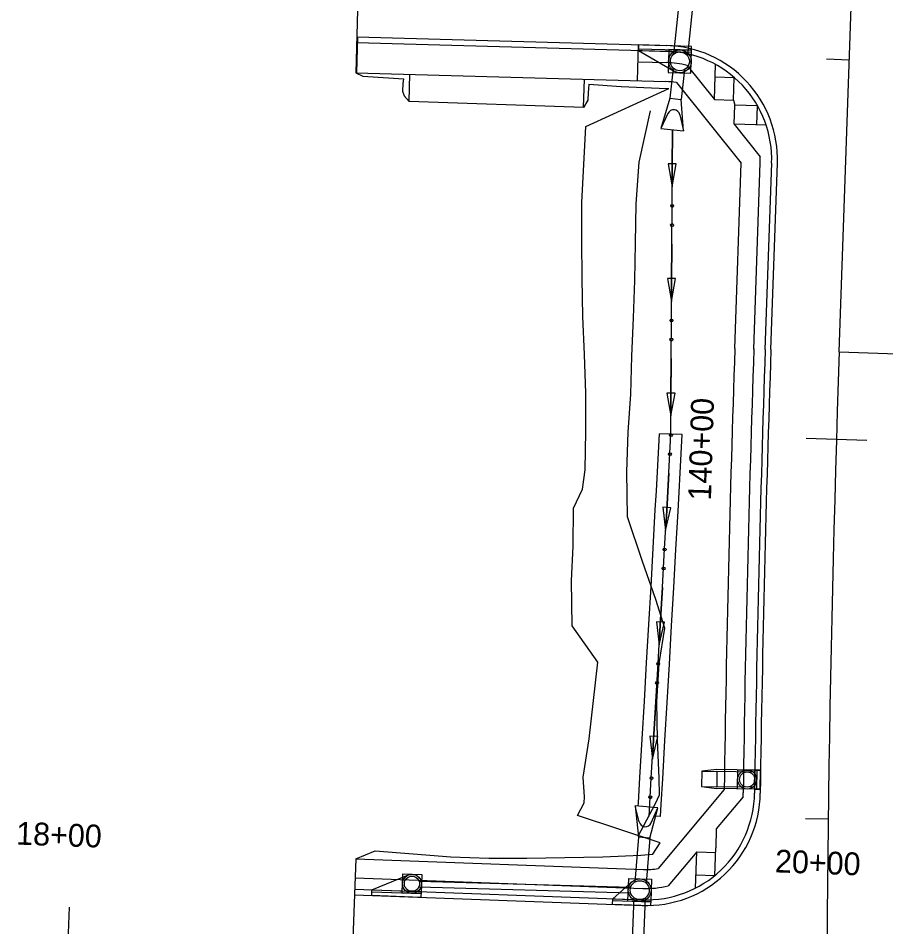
# Model space of a CAD drawing. Extents: x 979959 to 994833, y 1835619 to 1845316.
# Drawn here: x 992259.7 to 992488.3, y 1842625.6 to 1842864.9 of the extents above; entities that cross this region are included whole.
import ezdxf

# ---------------------------------------------------------------- set-up
doc = ezdxf.new("R2010")
doc.units = 0
for name, color, linetype in [('Future 5 Lane Construction Limits', 7, 'Continuous'), ('R_Drainage', 7, 'Continuous'), ('R_Horz Alg', 7, 'Continuous'), ('R_Horz Alg Annot', 7, 'Continuous'), ('R_Horz Alg Stationing', 7, 'Continuous'), ('R_Proposed Const Limits', 7, 'Continuous'), ('R_Proposed Road', 7, 'Continuous'), ('R_Special Ditch', 7, 'Continuous')]:
    doc.layers.add(name, color=color, linetype=linetype)

msp = doc.modelspace()

# ---------------------------------------------------------------- linework, layer by layer
at = {"layer": 'Future 5 Lane Construction Limits'}
for points in [[(992430.04, 1842704.32), (992427.7, 1842711.79), (992424.16, 1842721.86), (992420.25, 1842733.57), (992420.08, 1842745.46), (992420.46, 1842755.94), (992421.13, 1842765.94), (992421.36, 1842775.9), (992421.82, 1842785.98), (992422.18, 1842795.84), (992422.35, 1842805.73), (992422.51, 1842816.01), (992423.32, 1842826.99), (992426.26, 1842840.54)], [(992423.06, 1842649.49), (992427.64, 1842658.13), (992428.68, 1842660.39), (992428.57, 1842664.74), (992428.12, 1842674.83), (992428.01, 1842684.91), (992428.54, 1842694.98), (992430.04, 1842704.32)]]:
    msp.add_lwpolyline(points, dxfattribs=at)
at = {"layer": 'R_Drainage'}
for p, q in [((992436.04, 1842890.55), (992432.38, 1842855.46)), ((992439.73, 1842890.55), (992436.03, 1842855.08)), ((992423.11, 1842856.41), (992432.53, 1842850.98)), ((992423.12, 1842856.91), (992437.12, 1842856.49)), ((992432.31, 1842851.76), (992431.42, 1842843.86)), ((992435.29, 1842851.43), (992434.4, 1842843.53)), ((992431.42, 1842843.86), (992429.02, 1842835.93)), ((992431.42, 1842843.86), (992434.4, 1842843.53)), ((992434.98, 1842835.26), (992434.4, 1842843.53)), ((992430.9, 1842839.88), (992429.02, 1842835.93)), ((992434.03, 1842839.52), (992434.98, 1842835.26)), ((992429.02, 1842835.93), (992434.98, 1842835.26)), ((992434.67, 1842755.3), (992428.67, 1842755.48)), ((992439.79, 1842666.58), (992439.73, 1842662.58)), ((992443.8, 1842667.03), (992439.79, 1842666.58)), ((992439.79, 1842666.58), (992443.79, 1842666.53)), ((992443.79, 1842666.53), (992443.73, 1842662.53)), ((992453.79, 1842666.38), (992443.79, 1842666.53)), ((992454.3, 1842666.87), (992443.8, 1842667.03)), ((992449.22, 1842661.95), (992449.3, 1842666.95)), ((992453.79, 1842666.38), (992453.73, 1842662.38)), ((992454.3, 1842666.87), (992454.22, 1842661.87)), ((992439.73, 1842662.58), (992443.72, 1842662.03)), ((992439.73, 1842662.58), (992443.73, 1842662.53)), ((992454.22, 1842661.87), (992443.72, 1842662.03)), ((992453.73, 1842662.38), (992443.73, 1842662.53)), ((992453.72, 1842661.88), (992455.22, 1842661.86)), ((992428.25, 1842656.97), (992422.27, 1842657.46)), ((992422.27, 1842657.46), (992423.1, 1842649.22)), ((992423.35, 1842653.23), (992422.27, 1842657.46)), ((992426.09, 1842648.97), (992428.25, 1842656.97)), ((992426.49, 1842652.97), (992428.25, 1842656.97)), ((992428.91, 1842654.66), (992427.65, 1842654.73)), ((992423.1, 1842649.22), (992422.19, 1842637.42)), ((992426.09, 1842648.97), (992423.1, 1842649.22)), ((992426.09, 1842648.97), (992425.17, 1842637.09)), ((992361.08, 1842639.56), (992366.07, 1842639.38)), ((992352.92, 1842635.35), (992362.54, 1842639.28)), ((992365.36, 1842637.67), (992421.1, 1842636.09)), ((992416.37, 1842633.03), (992421.48, 1842637.52)), ((992352.9, 1842634.85), (992365.89, 1842634.38)), ((992365.32, 1842636.17), (992421.06, 1842634.59)), ((992416.36, 1842632.53), (992426.35, 1842632.16)), ((992421.89, 1842633.32), (992420.71, 1842601.17)), ((992424.89, 1842633.21), (992423.7, 1842601.06))]:
    msp.add_line(p, q, dxfattribs=at)
for points in [[(992423.11, 1842856.41), (992437.1, 1842855.99), (992437.14, 1842857.49), (992423.15, 1842857.91)], [(992430.94, 1842850.67), (992436.94, 1842850.5), (992437.12, 1842856.49), (992431.12, 1842856.67)], [(992449.22, 1842661.95), (992449.3, 1842666.95), (992454.3, 1842666.87), (992454.22, 1842661.87)], [(992453.72, 1842661.88), (992453.8, 1842666.88), (992455.3, 1842666.86), (992455.22, 1842661.86)], [(992361.08, 1842639.56), (992366.07, 1842639.38), (992365.89, 1842634.38), (992360.89, 1842634.56)], [(992420.57, 1842638.38), (992426.57, 1842638.16), (992426.35, 1842632.16), (992420.35, 1842632.38)], [(992352.92, 1842635.35), (992365.91, 1842634.88), (992365.85, 1842633.38), (992352.86, 1842633.86)], [(992416.37, 1842633.03), (992426.37, 1842632.66), (992426.31, 1842631.16), (992416.32, 1842631.53)]]:
    msp.add_lwpolyline(points, close=True, dxfattribs=at)
for points in [[(992423.07, 1842657.4), (992423.12, 1842658.24), (992423.52, 1842664.95), (992424.12, 1842675.02), (992424.71, 1842685.09), (992425.29, 1842695.16), (992425.87, 1842705.23), (992426.44, 1842715.29), (992427.01, 1842725.36), (992427.57, 1842735.42), (992427.85, 1842740.46), (992428.12, 1842745.49), (992428.67, 1842755.47), (992428.67, 1842755.48)], [(992428.91, 1842654.66), (992429.11, 1842657.88), (992429.51, 1842664.59), (992430.11, 1842674.67), (992430.7, 1842684.74), (992431.28, 1842694.81), (992431.86, 1842704.88), (992432.43, 1842714.95), (992433, 1842725.02), (992433.56, 1842735.09), (992433.84, 1842740.13), (992434.11, 1842745.16), (992434.67, 1842755.3)], [(992455.22, 1842661.86), (992455.3, 1842666.86), (992453.8, 1842666.88), (992453.72, 1842661.88)]]:
    msp.add_lwpolyline(points, dxfattribs=at)
for centre, radius in [((992434.03, 1842853.58), 3), ((992434.03, 1842853.58), 3), ((992434.03, 1842853.58), 2.5), ((992434.03, 1842853.58), 2.5), ((992451.76, 1842664.41), 2.5), ((992451.76, 1842664.41), 2.5), ((992451.76, 1842664.41), 2), ((992451.76, 1842664.41), 2), ((992363.48, 1842636.97), 2.5), ((992363.48, 1842636.97), 2.5), ((992363.48, 1842636.97), 2), ((992363.48, 1842636.97), 2), ((992423.46, 1842635.27), 3), ((992423.46, 1842635.27), 3), ((992423.46, 1842635.27), 2.5), ((992423.46, 1842635.27), 2.5)]:
    msp.add_circle(centre, radius, dxfattribs=at)
for centre, start, end in [((992432.4, 1842839.16), 12.6066, 154.5213), ((992424.96, 1842653.64), 194.3558, 336.2706)]:
    msp.add_arc(centre, 1.67, start, end, dxfattribs=at)
at = {"layer": 'R_Horz Alg'}
msp.add_line((992476.02, 1842777.04), (992513.51, 1843870.41), dxfattribs=at)
msp.add_arc((998202.23, 1842580.69), 5729.58, 178.036106, 183.022805, dxfattribs=at)
at = {"layer": 'R_Horz Alg Annot'}
msp.add_lwpolyline([(992476.02, 1842777.04), (992605.94, 1842772.59)], dxfattribs=at)
at = {"layer": 'R_Horz Alg Stationing'}
for points in [[(992472.66, 1842854.21), (992478.66, 1842854.01)], [(992467.28, 1842754.31), (992483.28, 1842753.82)], [(992467.13, 1842654.17), (992473.13, 1842654.09)], [(992273.19, 1842630.77), (992272.6, 1842614.78)]]:
    msp.add_lwpolyline(points, dxfattribs=at)
at = {"layer": 'R_Proposed Const Limits'}
for points in [[(992348.65, 1842850.57), (992350.54, 1842849.69), (992358.62, 1842849.15), (992361.23, 1842848.96)], [(992361.23, 1842848.96), (992361.06, 1842847.72), (992360.99, 1842845.72), (992361.39, 1842844.45), (992362.7, 1842842.98)], [(992428.81, 1842647.75), (992407.06, 1842654.94), (992408.85, 1842658.31), (992408.88, 1842659.87), (992408.58, 1842665.03), (992410.11, 1842675.12), (992411.32, 1842685.21), (992412.45, 1842695.3), (992405.64, 1842704.9), (992405.52, 1842716.74), (992405.9, 1842725.91), (992406.03, 1842735.91), (992408.42, 1842740.91), (992409.1, 1842745.95), (992409.3, 1842756.06), (992409.31, 1842766.18), (992408.92, 1842776.32), (992408.52, 1842786.37), (992408.33, 1842796.39), (992408.18, 1842806.4), (992408.21, 1842816.4), (992408.74, 1842826.39), (992409.27, 1842836.38), (992431.09, 1842846.43)], [(992410.07, 1842847.57), (992409.98, 1842846.33), (992409.91, 1842845.33), (992409.77, 1842843.33), (992408.67, 1842841.4)], [(992410.07, 1842847.57), (992418.58, 1842846.92), (992428.57, 1842846.54), (992431.09, 1842846.43)], [(992348.71, 1842643.51), (992353.79, 1842645.65), (992363.76, 1842644.86), (992373.74, 1842644.06), (992383.73, 1842643.68), (992393.74, 1842643.73), (992403.75, 1842643.85), (992413.77, 1842644.05), (992423.79, 1842644.51), (992426.92, 1842644.78), (992428.81, 1842647.75)]]:
    msp.add_lwpolyline(points, dxfattribs=at)
at = {"layer": 'R_Proposed Road'}
for p, q in [((992349.99, 1842897.56), (992348.65, 1842850.57)), ((992348.91, 1842850.57), (992349.18, 1842860.06)), ((992348.92, 1842860.07), (992430.59, 1842857.75)), ((992348.88, 1842858.57), (992430.54, 1842856.25)), ((992422.88, 1842848.46), (992423.15, 1842857.96)), ((992423.02, 1842853.46), (992430.46, 1842853.25)), ((992443.17, 1842843.49), (992443.44, 1842852.75)), ((992348.65, 1842850.57), (992430.32, 1842848.25)), ((992362.7, 1842842.98), (992362.9, 1842850.17)), ((992435.95, 1842852.49), (992443.17, 1842843.49)), ((992408.67, 1842841.4), (992408.89, 1842848.86)), ((992433.17, 1842847.97), (992450.21, 1842826.73)), ((992443.34, 1842849.49), (992448.34, 1842849.34)), ((992448.17, 1842843.35), (992448.34, 1842849.34)), ((992408.67, 1842841.4), (992362.7, 1842842.98)), ((992443.17, 1842843.49), (992448.17, 1842843.35)), ((992448.17, 1842843.35), (992448.52, 1842842.04)), ((992448.35, 1842837.04), (992448.52, 1842842.04)), ((992454.52, 1842841.83), (992448.52, 1842842.04)), ((992454.34, 1842836.83), (992454.52, 1842841.83)), ((992456.78, 1842836.75), (992448.35, 1842837.04)), ((992448.35, 1842837.04), (992455.22, 1842828.47)), ((992448.54, 1842777.98), (992450.21, 1842826.73)), ((992453.53, 1842777.81), (992455.22, 1842826.88)), ((992456.53, 1842777.71), (992458.22, 1842826.78)), ((992458.03, 1842777.66), (992459.71, 1842826.73)), ((992445.73, 1842661.75), (992428.28, 1842640.95)), ((992450.68, 1842659.88), (992443.59, 1842651.43)), ((992443.59, 1842651.43), (992443.53, 1842646.43)), ((992438.49, 1842645.35), (992430.97, 1842636.38)), ((992438.14, 1842635.82), (992438.49, 1842645.35)), ((992438.49, 1842645.35), (992443.49, 1842645.17)), ((992443.27, 1842639.17), (992443.53, 1842646.43)), ((992348.71, 1842643.51), (992346.98, 1842596.54)), ((992348.71, 1842643.51), (992424.47, 1842640.74)), ((992348.52, 1842638.52), (992424.28, 1842635.74)), ((992438.27, 1842639.35), (992443.27, 1842639.17)), ((992348.41, 1842635.52), (992424.17, 1842632.74)), ((992348.36, 1842634.02), (992424.12, 1842631.24))]:
    msp.add_line(p, q, dxfattribs=at)
for centre, radius, start, end in [((992429.73, 1842827.76), 30, 358.0361, 88.3694), ((992429.73, 1842827.76), 28.5, 358.0361, 88.3694), ((992429.73, 1842827.76), 25.5, 75.8794, 88.3694), ((992429.73, 1842827.76), 20.5, 80.3487, 88.3694), ((992429.73, 1842827.76), 25.5, 358.0361, 1.6001), ((998202.23, 1842580.69), 5757.08, 178.036106, 179.193225), ((998202.23, 1842580.69), 5752.08, 178.036106, 179.201336), ((998202.23, 1842580.69), 5749.08, 178.036106, 179.201336), ((998202.23, 1842580.69), 5747.58, 178.036106, 179.201336), ((992425.22, 1842661.22), 30, 267.9024, 359.2013), ((992425.22, 1842661.22), 28.5, 267.9024, 359.2013), ((992425.22, 1842661.22), 25.5, 356.9794, 359.2013), ((992425.22, 1842661.22), 20.5, 267.9024, 278.5888), ((992425.22, 1842661.22), 25.5, 267.9024, 283.0361)]:
    msp.add_arc(centre, radius, start, end, dxfattribs=at)
at = {"layer": 'R_Special Ditch'}
for p, q in [((992433.1, 1842826.54), (992430.97, 1842826.55)), ((992430.97, 1842826.55), (992432, 1842820.52)), ((992432, 1842820.52), (992433.1, 1842826.54)), ((992432.92, 1842796.36), (992430.8, 1842796.38)), ((992430.8, 1842796.38), (992431.83, 1842790.34)), ((992431.83, 1842790.34), (992432.92, 1842796.36)), ((992432.76, 1842766.19), (992430.63, 1842766.2)), ((992430.63, 1842766.2), (992431.68, 1842760.17)), ((992431.68, 1842760.17), (992432.76, 1842766.19)), ((992431.67, 1842735.99), (992429.55, 1842736.11)), ((992429.55, 1842736.11), (992430.27, 1842730.03)), ((992430.27, 1842730.03), (992431.67, 1842735.99)), ((992429.98, 1842705.86), (992427.85, 1842705.98)), ((992427.85, 1842705.98), (992428.57, 1842699.9)), ((992428.57, 1842699.9), (992429.98, 1842705.86)), ((992428.23, 1842675.73), (992426.11, 1842675.86)), ((992426.11, 1842675.86), (992426.81, 1842669.78)), ((992426.81, 1842669.78), (992428.23, 1842675.73))]:
    msp.add_line(p, q, dxfattribs=at)
for points in [[(992425.91, 1842654.7), (992426.11, 1842658.06), (992426.51, 1842664.77), (992427.11, 1842674.84), (992427.7, 1842684.92), (992428.29, 1842694.99), (992428.87, 1842705.06), (992429.44, 1842715.12), (992430, 1842725.19), (992430.56, 1842735.26), (992430.84, 1842740.29), (992431.12, 1842745.32), (992431.67, 1842755.39), (992431.69, 1842765.47), (992431.74, 1842775.55), (992431.8, 1842785.57), (992431.86, 1842795.58), (992431.91, 1842805.58), (992431.97, 1842815.59), (992432.03, 1842825.59), (992432.09, 1842835.59)], [(992432.09, 1842835.59), (992432.03, 1842825.59), (992432, 1842820.52)], [(992431.91, 1842805.41), (992431.86, 1842795.58), (992431.83, 1842790.34)], [(992431.91, 1842805.45), (992431.91, 1842805.41)], [(992431.74, 1842775.23), (992431.69, 1842765.47), (992431.68, 1842760.17)], [(992431.74, 1842775.27), (992431.74, 1842775.24)], [(992431.1, 1842745.07), (992430.84, 1842740.29), (992430.56, 1842735.26), (992430.27, 1842730.03)], [(992431.11, 1842745.11), (992431.1, 1842745.07)], [(992429.43, 1842714.95), (992428.87, 1842705.06), (992428.57, 1842699.9)], [(992429.43, 1842714.98), (992429.43, 1842714.95)], [(992427.7, 1842684.82), (992427.11, 1842674.84), (992426.81, 1842669.78)], [(992427.7, 1842684.86), (992427.7, 1842684.82)]]:
    msp.add_lwpolyline(points, dxfattribs=at)
for centre in [(992432.01, 1842815.49), (992431.98, 1842810.46), (992431.83, 1842785.31), (992431.81, 1842780.28), (992431.69, 1842755.14), (992431.42, 1842750.11), (992430.03, 1842725.01), (992429.75, 1842719.98), (992428.32, 1842694.88), (992428.03, 1842689.85), (992426.55, 1842664.75), (992426.25, 1842659.73)]:
    msp.add_circle(centre, 0.377, dxfattribs=at)

# ---------------------------------------------------------------- texts
at = {"layer": 'R_Horz Alg Stationing'}
for s, rotation, p in [('140+00', 88.266, (992442.22, 1842737.85)), ('18+00', 357.9024, (992259.14, 1842647.29)), ('20+00', 357.9024, (992459, 1842639.97))]:
    msp.add_text(s, height=6, rotation=rotation, dxfattribs=at).set_placement(p)

doc.saveas('drawing.dxf')
